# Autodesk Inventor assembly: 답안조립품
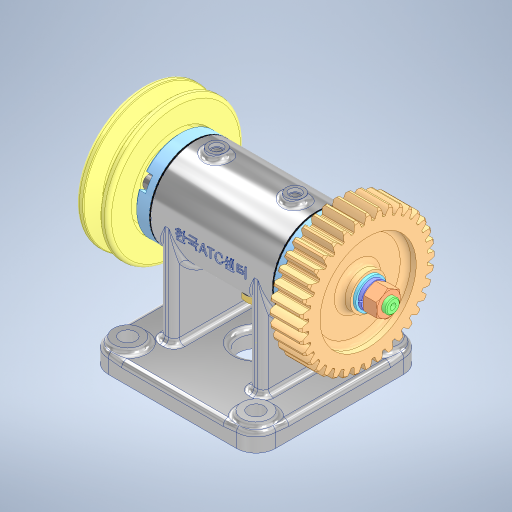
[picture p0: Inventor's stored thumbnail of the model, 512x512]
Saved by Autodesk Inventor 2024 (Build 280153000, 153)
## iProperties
Created: 2025-10
Part Number: 답안조립품
Document SubType Name: Assembly
Designer: EDU03
Author: EDU03
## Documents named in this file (16)
- C:\Users\EDU03\Desktop\751003V1002\답안조립품.iam
- C:\Users\EDU03\Desktop\751003V1002\본체.ipt
- C:\Users\EDU03\Desktop\751003V1002\축\축.ipt
- C:\Users\EDU03\Desktop\751003V1002\평행 키 3x3x12\평행 키 3x3x12.ipt
- C:\Users\EDU03\Desktop\751003V1002\깊은 홈 볼 베어링 6002\깊은 홈 볼 베어링 6002.ipt
- C:\Users\EDU03\Desktop\751003V1002\커버\커버.ipt
- C:\Users\EDU03\Desktop\751003V1002\오일 실 15 25 4\오일 실 15 25 4.ipt
- C:\Users\EDU03\Desktop\751003V1002\가스켓\가스켓.ipt
- C:\Users\EDU03\Desktop\751003V1002\스퍼 기어\스퍼 기어.ipt
- C:\Users\EDU03\Desktop\751003V1002\V 벨트 풀리\V 벨트 풀리.ipt
- C:\Users\EDU03\Desktop\751003V1002\평 와셔 M8\평 와셔 M8.ipt
- C:\Users\EDU03\Desktop\751003V1002\스프링 와셔 M8\스프링 와셔 M8.ipt
- C:\Users\EDU03\Desktop\751003V1002\6각 너트 M8x1\6각 너트 M8x1.ipt
- C:\Users\EDU03\Desktop\751003V1002\실링\실링.ipt
- C:\Users\EDU03\Desktop\751003V1002\6각 머리 볼트 M6x0.75x8\6각 머리 볼트 M6x0.75x8.ipt
- C:\Users\EDU03\Desktop\751003V1002\6각 구멍붙이 볼트 M4x10\6각 구멍붙이 볼트 M4x10.ipt
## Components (12 placed, 5 different names)
1. 가스켓:1
2. 가스켓:2
3. V 벨트 풀리:1
4. 6각 너트 M8x1:1
5. 6각 너트 M8x1:2
6. 6각 머리 볼트 M6x0.75x8:1
7. 6각 구멍붙이 볼트 M4x10:1
8. 6각 구멍붙이 볼트 M4x10:2
9. 6각 구멍붙이 볼트 M4x10:3
10. 6각 구멍붙이 볼트 M4x10:4
11. 6각 구멍붙이 볼트 M4x10:5
12. 6각 구멍붙이 볼트 M4x10:6
